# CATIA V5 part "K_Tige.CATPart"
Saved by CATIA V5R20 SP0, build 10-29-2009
Part number: Tige
Bounding box of the stored display mesh (mm): x -63 to -13, y 176.577 to 201.271, z -185.302 to -152.053
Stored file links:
  G:\Khaled_CFAO_2011\ST2M\ST2M_GR2\plakomicki\Khaled\CAD_ThinkMOTION\K_Tige.CATPart
  G:\Khaled_CFAO_2011\ST2M\ST2M_GR2\plakomicki\Khaled\CAD_ThinkMOTION\K_Jambe.CATProduct
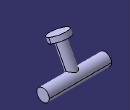
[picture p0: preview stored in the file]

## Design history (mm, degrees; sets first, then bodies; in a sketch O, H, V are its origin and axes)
Set1
  Plane1: linked copy from another document
  Point1: linked copy from another document
  Plane2: linked copy from another document
Body1 (main body)
  Sketch1 on Plane1, origin (0, 117.1921, -222.0481), H (1, 0, 0), V (0, 0.8844, 0.4668)
    circle A1 centre (-38, 89.4164) radius 4
    point P1 (-38, 89.4164)
    reference projected point E1 (-38, 89.4164) from Point1
    radius A1 = 4
    coincidence: P1 E1
  Pad1: profile Sketch1, direction (0, -0.4668, 0.8844), length 24
  Sketch2 on Plane2, origin (-38, 0, 0), H (0, 1, 0), V (0, 0, 1)
    circle A1 centre (196.2706, -180.3122) radius 5
    point P1 (196.2706, -180.3122)
    reference projected point E1 (196.2706, -180.3122) from Point1
    radius A1 = 5
    coincidence: E1 P1
  Pad2: profile Sketch2, direction (1, 0, 0), length 25, mirrored extent
  Sketch3 on end face of Pad1, origin (0, 105.9899, -200.8229), H (1, 0, 0), V (0, 0.8844, 0.4668)
    circle A1 centre (-38, 89.4164) radius 7.5
    point P1 (-38, 89.4164)
    reference projected point E1 (-38, 89.4164) from Point1
    radius A1 = 7.5
    coincidence: E1 P1
  Pad3: profile Sketch3, direction (0, -0.4668, 0.8844), length 4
